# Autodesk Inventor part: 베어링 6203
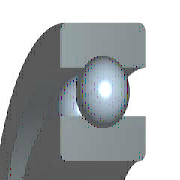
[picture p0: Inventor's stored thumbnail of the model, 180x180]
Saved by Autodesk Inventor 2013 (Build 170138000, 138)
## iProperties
IsCustomPart: 0
Created: 2014-10
Part Number: 베어링 6203
Material: 알루미늄 6061
Description: 깊은 그루브 볼 베어링
Document SubType Name: Modeling
Standard: KS B 2023
Designer: KYOUNG IL JANG
Standards Organization: KS
Language: ko-KR
Size Designation: 6203 - 17 x 40 x 12
Categories: <MemberInstance><Categories><Category DisplayName="샤프트 부품" InternalName="7f7aeb1f-a693-4053-b835-cee3144e0d98" Mnemonic="SHFT"><Category DisplayName="베어링" Inter
Density: 7.86 g/cm^3
Mass: 64.9809 g
Surface Area: 64.3582 cm^2
Volume: 8.26729 cm^3
Author: SeoGD™ [www.esajin.kr]
Revision Number: 1
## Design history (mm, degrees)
sketch "스케치" dims "d0" = 5.98 (= -0.26 x WD + 0.26 x BD)
  geometry: L1 (3.01, 14.25)-(8.99, 14.25); L2 (6, 14.25)-(6, 11.26); L3 (6, 14.25)-(6, 17.24); L4 (3.778, 12.249)-(0, 12.249); L5 (0, 8.5)-(12, 8.5); L6 (3.778, 16.251)-(0, 16.251); L7 (0, 20)-(12, 20); L8 (12, 8.5)-(12, 12.249); L9 (8.222, 12.249)-(12, 12.249); L10 (8.222, 16.251)-(12, 16.251); L11 (12, 20)-(12, 16.251); L12 (-1.4, 0)-(8.4, 0) reference; L13 (0, -0.3)-(0, 5.3) reference
  constraints: 22 end point, 4 point on line, 2 collinear, 2 perpendicular, 2 symmetric about line, 1 midpoint, 1 parallel, 14 other
  dimensions: "d9" = 17 diameter of L5 L12 (= WD); "d11" = 40 diameter of L7 L12 (= BD); "d12" = 12 distance between parallel lines of L8 L13 (= KB); "d13" = 24.498 diameter of L9 L12 (= 0.326 x BD + 0.674 x WD)
revolve "본체" stored, may be unused: angle "d6" = 90 deg
revolve "볼" stored, may be unused: angle "d7" = 90 deg
pattern_circular "IDS_ARRAYBALL[SIMPL:T]" dims angle "d3" = 360 deg
body "Solid1"
fillet "모깎기1" dims "d1" = 0.6 (= KRS)
other parameters: "WD" = 17 [user parameter; used in 5 equation terms], "BD" = 40 [user parameter; used in 5 equation terms], "KB" = 12 [user parameter; used in 1 equation term], "KRS" = 0.6 [user parameter; used in 1 equation term], "d4" = 0, "d5" = 0, "d8" = 0, "d14" = 0, "d15" = 0, "BBA" = 0 [user parameter], "BC0" = 4750000 [user parameter], "BC" = 9560000 [user parameter], "WR" = 8.5 (= 0.5 x WD) [user parameter]
